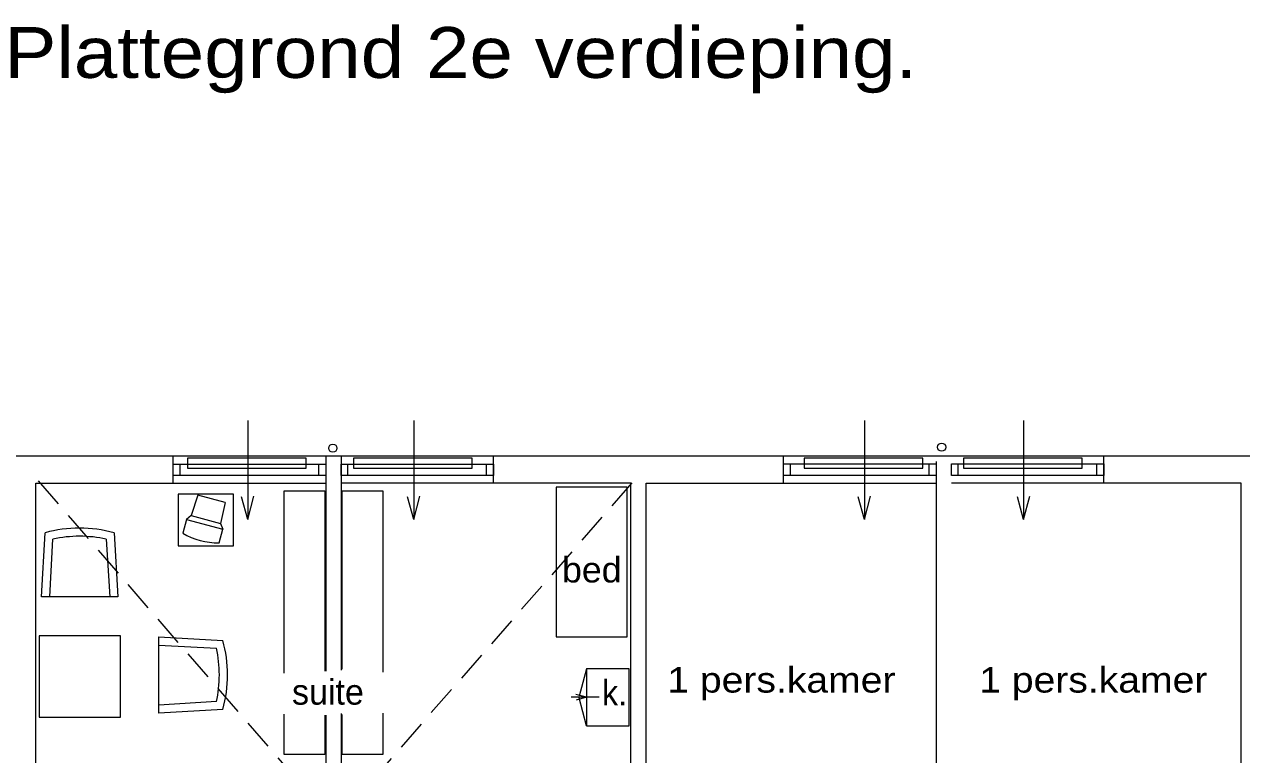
# Model space of a CAD drawing. Extents: x 295824 to 414724, y 24924 to 109024.
# Drawn here: x 301977 to 313944, y 76222 to 83404 of the extents above; entities that cross this region are included whole.
import ezdxf

# ---------------------------------------------------------------- set-up
doc = ezdxf.new("R2010")
doc.units = 0
doc.header["$LTSCALE"] = 100
doc.linetypes.add('MEDIUM_DASHED', pattern=[4.5, 3, -1.5])
doc.layers.add('24', color=7, linetype='Continuous', lineweight=13)
doc.layers.add('61', color=7, linetype='Continuous', lineweight=13)

msp = doc.modelspace()

# ---------------------------------------------------------------- linework, layer by layer
at = {"layer": '24'}
for p, q in [((304172.2, 78534.5), (304112.5, 78756.9)), ((305804.5, 78534.5), (305744.9, 78756.9)), ((310235, 78534.5), (310175.4, 78756.9)), ((311800.7, 78534.5), (311741.1, 78756.9))]:
    msp.add_line(p, q, dxfattribs=at)
for points in [[(304172.2, 79509.5), (304172.2, 78534.5), (304233.8, 78764.7)], [(305804.5, 79509.5), (305804.5, 78534.5), (305866.2, 78764.7)], [(310235, 79509.5), (310235, 78534.5), (310296.7, 78764.7)], [(311800.7, 79509.5), (311800.7, 78534.5), (311862.4, 78764.7)]]:
    msp.add_lwpolyline(points, dxfattribs=at)
for points in [[(303580.8, 79038.7), (304746.8, 79038.7), (304746.8, 79138.7), (303580.8, 79138.7)], [(305213.2, 79038.7), (306379.1, 79038.7), (306379.1, 79138.7), (305213.2, 79138.7)], [(309643.7, 79038.7), (310809.7, 79038.7), (310809.7, 79138.7), (309643.7, 79138.7)], [(311209.4, 79038.7), (312375.4, 79038.7), (312375.4, 79138.7), (311209.4, 79138.7)]]:
    msp.add_lwpolyline(points, close=True, dxfattribs=at)
at = {"layer": '61'}
for p, q in [((303441.2, 78890.6), (303441.2, 79160.6)), ((304940.1, 79159.3), (304940.1, 77044)), ((305090.1, 79159.3), (305090.1, 77053.9)), ((306589.5, 78890.8), (306589.5, 79160.8)), ((309441.4, 78890.8), (309441.4, 79160.8)), ((312589.8, 78890.8), (312589.8, 79160)), ((303508, 78966.5), (303508, 79080.3)), ((304873, 78965.9), (304873, 79079.9)), ((305156.5, 78966.8), (305156.5, 79080.8)), ((306520.9, 78966.5), (306520.9, 79080.2)), ((309508.3, 78969), (309508.3, 79082.9)), ((310873.3, 78968.4), (310873.3, 79082.4)), ((311156.8, 78969.4), (311156.8, 79083.4)), ((312521.1, 78969.1), (312521.1, 79082.7)), ((302090.1, 78890.8), (304940.1, 78890.8)), ((302090.1, 72179.9), (302090.1, 78890.8)), ((307940.1, 78890.8), (305090.1, 78890.8)), ((307940.1, 72179.6), (307940.1, 78890.8)), ((308090.1, 78890.8), (310940.1, 78890.8)), ((308090.1, 72179.8), (308090.1, 78890.8)), ((313940.1, 78890.8), (311090.1, 78890.8)), ((313940.1, 72179.8), (313940.1, 78890.8)), ((303680.7, 78774.9), (303616.6, 78574.7)), ((303951.1, 78702.4), (303680.7, 78774.9)), ((304529.6, 78815.4), (304929.6, 78815.4)), ((304529.6, 77024.4), (304529.6, 78815.4)), ((304929.6, 78815.4), (304929.6, 77044)), ((305099.7, 78815.4), (305499.7, 78815.4)), ((305099.7, 77063.7), (305099.7, 78815.4)), ((305499.7, 78815.4), (305499.7, 77034.2)), ((303951.1, 78702.4), (303906.4, 78497)), ((303569.9, 78535.4), (303533.7, 78400.5)), ((303616.6, 78574.7), (303569.9, 78535.4)), ((303569.9, 78535.4), (303927.3, 78439.7)), ((302145.9, 77775.2), (302180.8, 78404.6)), ((303891, 78304.4), (303927.3, 78439.7)), ((302226, 77775.2), (302257.4, 78341.2)), ((302782.2, 78341.1), (302815.7, 77775.2)), ((303299, 77380), (303928.4, 77345.1)), ((303299, 77299.9), (303865, 77268.5)), ((307503.4, 77067.3), (307431.1, 76797.3)), ((303864.9, 76743.7), (303299, 76710.2)), ((307629.3, 76787.3), (307353.3, 76787.3)), ((307503.4, 76787.3), (307399.6, 76815.1)), ((307503.4, 76787.3), (307400, 76759.6)), ((307503.4, 76507.3), (307430.4, 76779.9)), ((304529.6, 76223.5), (304529.6, 76621.1)), ((304929.6, 76611.3), (304929.6, 76223.5)), ((304940.1, 76611.3), (304940.1, 75450.1)), ((305090.1, 76626), (305090.1, 75450.1)), ((305099.7, 76223.5), (305099.7, 76616.2)), ((305499.7, 76630.9), (305499.7, 76223.5)), ((304929.6, 76223.5), (304529.6, 76223.5)), ((305499.7, 76223.5), (305099.7, 76223.5))]:
    msp.add_line(p, q, dxfattribs=at)
at = {"layer": '61', "linetype": 'MEDIUM_DASHED'}
for p, q in [((302112.4, 78915.1), (307930.8, 72187.9)), ((307950.5, 78895.5), (302112.4, 72207.6))]:
    msp.add_line(p, q, dxfattribs=at)
at = {"layer": '61'}
for points in [[(301796.6, 66927.7), (301820.1, 79160.8), (332210.1, 79160.8)], [(310940.1, 79104.8), (310940.1, 74040.8), (309025.1, 74040.8), (309025.1, 73890.8), (313005.2, 73890.8)], [(303616.6, 78574.7), (303906.4, 78497), (303927.3, 78439.7)], [(302858.6, 78404.5), (302895.8, 77775.2), (302145.9, 77775.2)], [(303928.3, 76667.3), (303299, 76630.1), (303299, 77380)]]:
    msp.add_lwpolyline(points, dxfattribs=at)
for points in [[(303441.2, 78966.3), (303441.2, 79080.3), (304939.8, 79080.3), (304939.8, 78966.3)], [(305090.2, 78966.5), (305090.2, 79080.5), (306589.6, 79080.5), (306589.6, 78966.5)], [(309441.5, 78968.9), (309441.5, 79082.9), (310940.1, 79082.9), (310940.1, 78968.9)], [(311090.5, 78969.1), (311090.5, 79083.1), (312589.8, 79083.1), (312589.8, 78969.1)], [(304033.8, 78784.9), (303487.6, 78784.9), (303487.6, 78276.9), (304033.8, 78276.9)], [(307203.8, 77382), (307903.8, 77382), (307903.8, 78852), (307203.8, 78852)], [(302123.2, 76589.9), (302923.2, 76589.9), (302923.2, 77389.9), (302123.2, 77389.9)], [(307923.4, 77067.3), (307503.4, 77067.3), (307503.4, 76507.3), (307923.4, 76507.3)]]:
    msp.add_lwpolyline(points, close=True, dxfattribs=at)
for centre in [(305009.5, 79235.9), (310995, 79245.8)]:
    msp.add_circle(centre, 40, dxfattribs=at)
for centre, radius, start, end in [((302519.6, 77164.8), 1285.2, 74.70731, 105.28507), ((303896, 79035.1), 730.8, 240.27982, 269.60839), ((302519.6, 77164.8), 1205.2, 77.41626, 102.56606), ((302688.6, 77006.3), 1285.2, 344.70731, 15.28507), ((302688.6, 77006.3), 1205.2, 347.41626, 12.56606)]:
    msp.add_arc(centre, radius, start, end, dxfattribs=at)

# ---------------------------------------------------------------- texts
for s, height, width, p in [('Plattegrond 2e verdieping.', 500, 1.15, (301778.6, 82877.5)), ('bed', 250, 1.05, (307262.5, 77915.6)), ('1 pers.kamer', 250, 1.15, (308297.5, 76832.7)), ('1 pers.kamer', 250, 1.15, (311364, 76832.7)), ('k.', 250, 0.95, (307655.7, 76705.8))]:
    msp.add_text(s, height=height, dxfattribs=dict(at, width=width)).set_placement(p)
msp.add_text('suite', height=250, dxfattribs=at).set_placement((304608.3, 76713.9))

doc.saveas('drawing.dxf')
